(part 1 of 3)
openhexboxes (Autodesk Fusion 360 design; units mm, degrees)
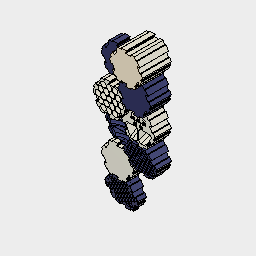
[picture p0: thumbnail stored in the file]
sketch "Skizze1"
  line L1 (20.2073, 35) -> (-20.2073, 35)
  line L2 (0, 0) -> (20.2073, 35)
  line L3 (-20.2073, 35) -> (0, 0)
  line L4 (0, 42) -> (0, 0)
  line L5 (-12.1732, 35) -> (-20.2073, 35)
  line L6 (-12.0866, 36.95) -> (-11.567, 36.05)
  line L7 (0.5196, 38) -> (-11.4804, 38)
  line L8 (-1.1258, 33.05) -> (1.1258, 36.95)
  line L9 (11.4804, 32) -> (-0.5196, 32)
  line L10 (11.567, 33.95) -> (12.0866, 33.05)
  line L11 (12.1732, 35) -> (20.2073, 35)
  line L12 (-20.2073, 35) -> (-40.4145, 0)
  line L13 (-29.1851, 15.55) -> (-31.4367, 19.45)
  line L14 (-24.2243, 28.0423) -> (-20.2073, 35)
  line L15 (-23.6181, 26.9923) -> (-22.5788, 26.9923)
  line L16 (-21.9726, 25.9423) -> (-27.9726, 15.55)
  line L17 (-32.6492, 19.45) -> (-38.6492, 9.0577)
  line L18 (-38.0429, 8.0077) -> (-37.0037, 8.0077)
  line L19 (-36.3975, 6.9577) -> (-40.4145, 0)
  line L20 (-40.4145, 0) -> (-20.2073, -35)
  line L21 (-28.0592, -17.5) -> (-32.5626, -17.5)
  line L22 (-36.3975, -6.9577) -> (-40.4145, 0)
  line L23 (-35.1851, -6.9577) -> (-34.6654, -6.0577)
  line L24 (-33.453, -6.0577) -> (-27.453, -16.45)
  line L25 (-33.1688, -18.55) -> (-27.1688, -28.9423)
  line L26 (-25.9563, -28.9423) -> (-25.4367, -28.0423)
  line L27 (-24.2243, -28.0423) -> (-20.2073, -35)
  line L28 (-20.2073, -35) -> (20.2073, -35)
  line L29 (1.1258, -33.05) -> (-1.1258, -36.95)
  line L30 (-12.1732, -35) -> (-20.2073, -35)
  line L31 (-11.567, -33.95) -> (-12.0866, -33.05)
  line L32 (-11.4804, -32) -> (0.5196, -32)
  line L33 (-0.5196, -38) -> (11.4804, -38)
  line L34 (12.0866, -36.95) -> (11.567, -36.05)
  line L35 (12.1732, -35) -> (20.2073, -35)
  line L36 (20.2073, -35) -> (40.4145, 0)
  line L37 (29.1851, -15.55) -> (31.4367, -19.45)
  line L38 (24.2243, -28.0423) -> (20.2073, -35)
  line L39 (23.6181, -26.9923) -> (22.5788, -26.9923)
  line L40 (21.9726, -25.9423) -> (27.9726, -15.55)
  line L41 (32.6492, -19.45) -> (38.6492, -9.0577)
  line L42 (38.0429, -8.0077) -> (37.0037, -8.0077)
  line L43 (36.3975, -6.9577) -> (40.4145, 0)
  line L44 (40.4145, 0) -> (20.2073, 35)
  line L45 (28.0592, 17.5) -> (32.5626, 17.5)
  line L46 (36.3975, 6.9577) -> (40.4145, 0)
  line L47 (35.1851, 6.9577) -> (34.6654, 6.0577)
  line L48 (33.453, 6.0577) -> (27.453, 16.45)
  line L49 (33.1688, 18.55) -> (27.1688, 28.9423)
  line L50 (25.9563, 28.9423) -> (25.4367, 28.0423)
  line L51 (24.2243, 28.0423) -> (20.2073, 35)
  arc A1 centre (-12.1732, 35.7) radius 0.7 clockwise from (-11.567, 36.05) to (-12.1732, 35)
  arc A2 centre (-11.4804, 37.3) radius 0.7 clockwise from (-12.0866, 36.95) to (-11.4804, 38)
  arc A3 centre (0.5196, 37.3) radius 0.7 clockwise from (0.5196, 38) to (1.1258, 36.95)
  arc A4 centre (-0.5196, 32.7) radius 0.7 clockwise from (-0.5196, 32) to (-1.1258, 33.05)
  arc A5 centre (11.4804, 32.7) radius 0.7 clockwise from (12.0866, 33.05) to (11.4804, 32)
  arc A6 centre (12.1732, 34.3) radius 0.7 clockwise from (11.567, 33.95) to (12.1732, 35)
  arc A7 centre (-22.5788, 26.2923) radius 0.7 clockwise from (-22.5788, 26.9923) to (-21.9726, 25.9423)
  arc A8 centre (-37.0037, 7.3077) radius 0.7 clockwise from (-37.0037, 8.0077) to (-36.3975, 6.9577)
  arc A9 centre (-38.0429, 8.7077) radius 0.7 clockwise from (-38.0429, 8.0077) to (-38.6492, 9.0577)
  arc A10 centre (-23.6181, 27.6923) radius 0.7 clockwise from (-23.6181, 26.9923) to (-24.2243, 28.0423)
  arc A11 centre (-32.0429, 19.1) radius 0.7 clockwise from (-32.6492, 19.45) to (-31.4367, 19.45)
  arc A12 centre (-28.5788, 15.9) radius 0.7 clockwise from (-27.9726, 15.55) to (-29.1851, 15.55)
  arc A13 centre (-34.0592, -6.4077) radius 0.7 clockwise from (-34.6654, -6.0577) to (-33.453, -6.0577)
  arc A14 centre (-24.8305, -28.3923) radius 0.7 clockwise from (-25.4367, -28.0423) to (-24.2243, -28.0423)
  arc A15 centre (-26.5626, -28.5923) radius 0.7 clockwise from (-25.9563, -28.9423) to (-27.1688, -28.9423)
  arc A16 centre (-35.7913, -6.6077) radius 0.7 clockwise from (-35.1851, -6.9577) to (-36.3975, -6.9577)
  arc A17 centre (-32.5626, -18.2) radius 0.7 clockwise from (-33.1688, -18.55) to (-32.5626, -17.5)
  arc A18 centre (-28.0592, -16.8) radius 0.7 clockwise from (-27.453, -16.45) to (-28.0592, -17.5)
  arc A19 centre (-11.4804, -32.7) radius 0.7 clockwise from (-12.0866, -33.05) to (-11.4804, -32)
  arc A20 centre (12.1732, -35.7) radius 0.7 clockwise from (11.567, -36.05) to (12.1732, -35)
  arc A21 centre (11.4804, -37.3) radius 0.7 clockwise from (12.0866, -36.95) to (11.4804, -38)
  arc A22 centre (-12.1732, -34.3) radius 0.7 clockwise from (-11.567, -33.95) to (-12.1732, -35)
  arc A23 centre (-0.5196, -37.3) radius 0.7 clockwise from (-0.5196, -38) to (-1.1258, -36.95)
  arc A24 centre (0.5196, -32.7) radius 0.7 clockwise from (0.5196, -32) to (1.1258, -33.05)
  arc A25 centre (22.5788, -26.2923) radius 0.7 clockwise from (22.5788, -26.9923) to (21.9726, -25.9423)
  arc A26 centre (37.0037, -7.3077) radius 0.7 clockwise from (37.0037, -8.0077) to (36.3975, -6.9577)
  arc A27 centre (38.0429, -8.7077) radius 0.7 clockwise from (38.0429, -8.0077) to (38.6492, -9.0577)
  arc A28 centre (23.6181, -27.6923) radius 0.7 clockwise from (23.6181, -26.9923) to (24.2243, -28.0423)
  arc A29 centre (32.0429, -19.1) radius 0.7 clockwise from (32.6492, -19.45) to (31.4367, -19.45)
  arc A30 centre (28.5788, -15.9) radius 0.7 clockwise from (27.9726, -15.55) to (29.1851, -15.55)
  arc A31 centre (34.0592, 6.4077) radius 0.7 clockwise from (34.6654, 6.0577) to (33.453, 6.0577)
  arc A32 centre (24.8305, 28.3923) radius 0.7 clockwise from (25.4367, 28.0423) to (24.2243, 28.0423)
  arc A33 centre (26.5626, 28.5923) radius 0.7 clockwise from (25.9563, 28.9423) to (27.1688, 28.9423)
  arc A34 centre (35.7913, 6.6077) radius 0.7 clockwise from (35.1851, 6.9577) to (36.3975, 6.9577)
  arc A35 centre (32.5626, 18.2) radius 0.7 clockwise from (33.1688, 18.55) to (32.5626, 17.5)
  arc A36 centre (28.0592, 16.8) radius 0.7 clockwise from (27.453, 16.45) to (28.0592, 17.5)
  point P1 (0, 0)
  point P11 (-11.4804, 38)
  point P13 (0.5196, 38)
  point P17 (-0.5196, 32)
  point P19 (11.4804, 32)
  dimension "d1" angle L2 L3 = 60
  dimension "d2" distance P1 L1 = 35
  dimension "d3" angle L3 L4 = 30
  dimension "d4" radius A1 = 0.7
  dimension "d5" distance L1 L7 = 3
  dimension "d6" distance L1 L9 = 3
  dimension "d7" angle L1 L8 = 60
  dimension "d8" angle L1 L10 = 60 (= "d7")
  dimension "d10" distance P11 P13 = 12
  dimension "d11" distance P17 P19 = 12 (= "d10")
  dimension "d13" C-Pattern1-Angle = 360
extrude "Extrusion1" sketch "Skizze1" profile of L5 L6 L7 L8 L9 L10 L11 A1 A2 A3 A4 A5 A6 A7 A8 A9 A10 L13 L14 L15 A11 A12 L16 L17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 blind 70 bodies "Basis"
sketch "Skizze2" plane through (0, 0, 70) normal (0, 0, 1) x axis (1, 0, 0)
  line L1 (12.0866, 33.05) -> (11.567, 33.95)
  line L2 (-0.5196, 32) -> (11.4804, 32)
  line L3 (1.1258, 36.95) -> (-1.1258, 33.05)
  line L4 (-11.4804, 38) -> (0.5196, 38)
  line L5 (-11.567, 36.05) -> (-12.0866, 36.95)
  line L6 (-20.2073, 35) -> (-12.1732, 35)
  line L7 (-24.2243, 28.0423) -> (-20.2073, 35)
  line L8 (-22.5788, 26.9923) -> (-23.6181, 26.9923)
  line L9 (-27.9726, 15.55) -> (-21.9726, 25.9423)
  line L10 (-31.4367, 19.45) -> (-29.1851, 15.55)
  line L11 (-38.6492, 9.0577) -> (-32.6492, 19.45)
  line L12 (-37.0037, 8.0077) -> (-38.0429, 8.0077)
  line L13 (-40.4145, 0) -> (-36.3975, 6.9577)
  line L14 (-36.3975, -6.9577) -> (-40.4145, 0)
  line L15 (-34.6654, -6.0577) -> (-35.1851, -6.9577)
  line L16 (-27.453, -16.45) -> (-33.453, -6.0577)
  line L17 (-32.5626, -17.5) -> (-28.0592, -17.5)
  line L18 (-27.1688, -28.9423) -> (-33.1688, -18.55)
  line L19 (-25.4367, -28.0423) -> (-25.9563, -28.9423)
  line L20 (-20.2073, -35) -> (-24.2243, -28.0423)
  line L21 (-12.1732, -35) -> (-20.2073, -35)
  line L22 (-12.0866, -33.05) -> (-11.567, -33.95)
  line L23 (0.5196, -32) -> (-11.4804, -32)
  line L24 (-1.1258, -36.95) -> (1.1258, -33.05)
  line L25 (11.4804, -38) -> (-0.5196, -38)
  line L26 (11.567, -36.05) -> (12.0866, -36.95)
  line L27 (20.2073, -35) -> (12.1732, -35)
  line L28 (24.2243, -28.0423) -> (20.2073, -35)
  line L29 (22.5788, -26.9923) -> (23.6181, -26.9923)
  line L30 (27.9726, -15.55) -> (21.9726, -25.9423)
  line L31 (31.4367, -19.45) -> (29.1851, -15.55)
  line L32 (38.6492, -9.0577) -> (32.6492, -19.45)
  line L33 (37.0037, -8.0077) -> (38.0429, -8.0077)
  line L34 (40.4145, 0) -> (36.3975, -6.9577)
  line L35 (36.3975, 6.9577) -> (40.4145, 0)
  line L36 (34.6654, 6.0577) -> (35.1851, 6.9577)
  line L37 (27.453, 16.45) -> (33.453, 6.0577)
  line L38 (32.5626, 17.5) -> (28.0592, 17.5)
  line L39 (27.1688, 28.9423) -> (33.1688, 18.55)
  line L40 (25.4367, 28.0423) -> (25.9563, 28.9423)
  line L41 (20.2073, 35) -> (24.2243, 28.0423)
  line L42 (12.1732, 35) -> (20.2073, 35)
  arc A1 centre (12.1732, 34.3) radius 0.7 clockwise from (11.567, 33.95) to (12.1732, 35)
  arc A2 centre (11.4804, 32.7) radius 0.7 clockwise from (12.0866, 33.05) to (11.4804, 32)
  arc A3 centre (-0.5196, 32.7) radius 0.7 clockwise from (-0.5196, 32) to (-1.1258, 33.05)
  arc A4 centre (0.5196, 37.3) radius 0.7 clockwise from (0.5196, 38) to (1.1258, 36.95)
  arc A5 centre (-11.4804, 37.3) radius 0.7 clockwise from (-12.0866, 36.95) to (-11.4804, 38)
  arc A6 centre (-12.1732, 35.7) radius 0.7 clockwise from (-11.567, 36.05) to (-12.1732, 35)
  arc A7 centre (-23.6181, 27.6923) radius 0.7 clockwise from (-23.6181, 26.9923) to (-24.2243, 28.0423)
  arc A8 centre (-22.5788, 26.2923) radius 0.7 clockwise from (-22.5788, 26.9923) to (-21.9726, 25.9423)
  arc A9 centre (-28.5788, 15.9) radius 0.7 clockwise from (-27.9726, 15.55) to (-29.1851, 15.55)
  arc A10 centre (-32.0429, 19.1) radius 0.7 clockwise from (-32.6492, 19.45) to (-31.4367, 19.45)
  arc A11 centre (-38.0429, 8.7077) radius 0.7 clockwise from (-38.0429, 8.0077) to (-38.6492, 9.0577)
  arc A12 centre (-37.0037, 7.3077) radius 0.7 clockwise from (-37.0037, 8.0077) to (-36.3975, 6.9577)
  arc A13 centre (-35.7913, -6.6077) radius 0.7 clockwise from (-35.1851, -6.9577) to (-36.3975, -6.9577)
  arc A14 centre (-34.0592, -6.4077) radius 0.7 clockwise from (-34.6654, -6.0577) to (-33.453, -6.0577)
  arc A15 centre (-28.0592, -16.8) radius 0.7 clockwise from (-27.453, -16.45) to (-28.0592, -17.5)
  arc A16 centre (-32.5626, -18.2) radius 0.7 clockwise from (-33.1688, -18.55) to (-32.5626, -17.5)
  arc A17 centre (-26.5626, -28.5923) radius 0.7 clockwise from (-25.9563, -28.9423) to (-27.1688, -28.9423)
  arc A18 centre (-24.8305, -28.3923) radius 0.7 clockwise from (-25.4367, -28.0423) to (-24.2243, -28.0423)
  arc A19 centre (-12.1732, -34.3) radius 0.7 clockwise from (-11.567, -33.95) to (-12.1732, -35)
  arc A20 centre (-11.4804, -32.7) radius 0.7 clockwise from (-12.0866, -33.05) to (-11.4804, -32)
  arc A21 centre (0.5196, -32.7) radius 0.7 clockwise from (0.5196, -32) to (1.1258, -33.05)
  arc A22 centre (-0.5196, -37.3) radius 0.7 clockwise from (-0.5196, -38) to (-1.1258, -36.95)
  arc A23 centre (11.4804, -37.3) radius 0.7 clockwise from (12.0866, -36.95) to (11.4804, -38)
  arc A24 centre (12.1732, -35.7) radius 0.7 clockwise from (11.567, -36.05) to (12.1732, -35)
  arc A25 centre (23.6181, -27.6923) radius 0.7 clockwise from (23.6181, -26.9923) to (24.2243, -28.0423)
  arc A26 centre (22.5788, -26.2923) radius 0.7 clockwise from (22.5788, -26.9923) to (21.9726, -25.9423)
  arc A27 centre (28.5788, -15.9) radius 0.7 clockwise from (27.9726, -15.55) to (29.1851, -15.55)
  arc A28 centre (32.0429, -19.1) radius 0.7 clockwise from (32.6492, -19.45) to (31.4367, -19.45)
  arc A29 centre (38.0429, -8.7077) radius 0.7 clockwise from (38.0429, -8.0077) to (38.6492, -9.0577)
  arc A30 centre (37.0037, -7.3077) radius 0.7 clockwise from (37.0037, -8.0077) to (36.3975, -6.9577)
  arc A31 centre (35.7913, 6.6077) radius 0.7 clockwise from (35.1851, 6.9577) to (36.3975, 6.9577)
  arc A32 centre (34.0592, 6.4077) radius 0.7 clockwise from (34.6654, 6.0577) to (33.453, 6.0577)
  arc A33 centre (28.0592, 16.8) radius 0.7 clockwise from (27.453, 16.45) to (28.0592, 17.5)
  arc A34 centre (32.5626, 18.2) radius 0.7 clockwise from (33.1688, 18.55) to (32.5626, 17.5)
  arc A35 centre (26.5626, 28.5923) radius 0.7 clockwise from (25.9563, 28.9423) to (27.1688, 28.9423)
  arc A36 centre (24.8305, 28.3923) radius 0.7 clockwise from (25.4367, 28.0423) to (24.2243, 28.0423)
sketch "Skizze3" plane through (0, 0, 0) normal (0, 0, -1) x axis (-1, 0, 0)
  line L1 (-20.2073, 35) -> (-12.1732, 35)
  line L2 (-24.2243, 28.0423) -> (-20.2073, 35)
  line L3 (-25.9563, 28.9423) -> (-25.4367, 28.0423)
  line L4 (-33.1688, 18.55) -> (-27.1688, 28.9423)
  line L5 (-28.0592, 17.5) -> (-32.5626, 17.5)
  line L6 (-33.453, 6.0577) -> (-27.453, 16.45)
  line L7 (-35.1851, 6.9577) -> (-34.6654, 6.0577)
  line L8 (-40.4145, 0) -> (-36.3975, 6.9577)
  line L9 (-36.3975, -6.9577) -> (-40.4145, 0)
  line L10 (-38.0429, -8.0077) -> (-37.0037, -8.0077)
  line L11 (-32.6492, -19.45) -> (-38.6492, -9.0577)
  line L12 (-29.1851, -15.55) -> (-31.4367, -19.45)
  line L13 (-21.9726, -25.9423) -> (-27.9726, -15.55)
  line L14 (-23.6181, -26.9923) -> (-22.5788, -26.9923)
  line L15 (-20.2073, -35) -> (-24.2243, -28.0423)
  line L16 (-12.1732, -35) -> (-20.2073, -35)
  line L17 (-12.0866, -36.95) -> (-11.567, -36.05)
  line L18 (0.5196, -38) -> (-11.4804, -38)
  line L19 (-1.1258, -33.05) -> (1.1258, -36.95)
  line L20 (11.4804, -32) -> (-0.5196, -32)
  line L21 (11.567, -33.95) -> (12.0866, -33.05)
  line L22 (20.2073, -35) -> (12.1732, -35)
  line L23 (24.2243, -28.0423) -> (20.2073, -35)
  line L24 (25.9563, -28.9423) -> (25.4367, -28.0423)
  line L25 (33.1688, -18.55) -> (27.1688, -28.9423)
  line L26 (28.0592, -17.5) -> (32.5626, -17.5)
  line L27 (33.453, -6.0577) -> (27.453, -16.45)
  line L28 (35.1851, -6.9577) -> (34.6654, -6.0577)
  line L29 (40.4145, 0) -> (36.3975, -6.9577)
  line L30 (36.3975, 6.9577) -> (40.4145, 0)
  line L31 (38.0429, 8.0077) -> (37.0037, 8.0077)
  line L32 (32.6492, 19.45) -> (38.6492, 9.0577)
  line L33 (29.1851, 15.55) -> (31.4367, 19.45)
  line L34 (21.9726, 25.9423) -> (27.9726, 15.55)
  line L35 (23.6181, 26.9923) -> (22.5788, 26.9923)
  line L36 (20.2073, 35) -> (24.2243, 28.0423)
  line L37 (12.1732, 35) -> (20.2073, 35)
  line L38 (12.0866, 36.95) -> (11.567, 36.05)
  line L39 (-0.5196, 38) -> (11.4804, 38)
  line L40 (1.1258, 33.05) -> (-1.1258, 36.95)
  line L41 (-11.4804, 32) -> (0.5196, 32)
  line L42 (-11.567, 33.95) -> (-12.0866, 33.05)
  line L43 (-28.0592, 17.7) -> (-32.5626, 17.7)
  line L44 (-33.2798, 5.9577) -> (-27.2798, 16.35)
  line L45 (-35.3583, 6.8577) -> (-34.8386, 5.9577)
  line L46 (-40.1836, 0) -> (-36.2243, 6.8577)
  line L47 (-36.2243, -6.8577) -> (-40.1836, 0)
  line L48 (-38.0429, -8.2077) -> (-37.0037, -8.2077)
  line L49 (-32.476, -19.35) -> (-38.476, -8.9577)
  line L50 (-29.3583, -15.45) -> (-31.6099, -19.35)
  line L51 (-21.7994, -25.8423) -> (-27.7994, -15.45)
  line L52 (-23.6181, -27.1923) -> (-22.5788, -27.1923)
  line L53 (-20.0918, -34.8) -> (-24.0511, -27.9423)
  line L54 (-12.1732, -34.8) -> (-20.0918, -34.8)
  line L55 (-11.9134, -37.05) -> (-11.3938, -36.15)
  line L56 (0.5196, -37.8) -> (-11.4804, -37.8)
  line L57 (-1.299, -33.15) -> (0.9526, -37.05)
  line L58 (11.4804, -31.8) -> (-0.5196, -31.8)
  line L59 (11.7402, -34.05) -> (12.2598, -33.15)
  line L60 (20.0918, -34.8) -> (12.1732, -34.8)
  line L61 (24.0511, -27.9423) -> (20.0918, -34.8)
  line L62 (26.1295, -28.8423) -> (25.6099, -27.9423)
  line L63 (32.9956, -18.45) -> (26.9956, -28.8423)
  line L64 (28.0592, -17.7) -> (32.5626, -17.7)
  line L65 (33.2798, -5.9577) -> (27.2798, -16.35)
  line L66 (35.3583, -6.8577) -> (34.8386, -5.9577)
  line L67 (40.1836, 0) -> (36.2243, -6.8577)
  line L68 (36.2243, 6.8577) -> (40.1836, 0)
  line L69 (38.0429, 8.2077) -> (37.0037, 8.2077)
  line L70 (32.476, 19.35) -> (38.476, 8.9577)
  line L71 (29.3583, 15.45) -> (31.6099, 19.35)
  line L72 (21.7994, 25.8423) -> (27.7994, 15.45)
  line L73 (23.6181, 27.1923) -> (22.5788, 27.1923)
  line L74 (20.0918, 34.8) -> (24.0511, 27.9423)
  line L75 (12.1732, 34.8) -> (20.0918, 34.8)
  line L76 (11.9134, 37.05) -> (11.3938, 36.15)
  line L77 (-0.5196, 37.8) -> (11.4804, 37.8)
  line L78 (1.299, 33.15) -> (-0.9526, 37.05)
  line L79 (-11.4804, 31.8) -> (0.5196, 31.8)
  line L80 (-11.7402, 34.05) -> (-12.2598, 33.15)
  line L81 (-20.0918, 34.8) -> (-12.1732, 34.8)
  line L82 (-24.0511, 27.9423) -> (-20.0918, 34.8)
  line L83 (-26.1295, 28.8423) -> (-25.6099, 27.9423)
  line L84 (-32.9956, 18.45) -> (-26.9956, 28.8423)
  arc A1 centre (-12.1732, 34.3) radius 0.7 clockwise from (-12.1732, 35) to (-11.567, 33.95)
  arc A2 centre (-24.8305, 28.3923) radius 0.7 clockwise from (-24.2243, 28.0423) to (-25.4367, 28.0423)
  arc A3 centre (-26.5626, 28.5923) radius 0.7 clockwise from (-27.1688, 28.9423) to (-25.9563, 28.9423)
  arc A4 centre (-32.5626, 18.2) radius 0.7 clockwise from (-32.5626, 17.5) to (-33.1688, 18.55)
  arc A5 centre (-28.0592, 16.8) radius 0.7 clockwise from (-28.0592, 17.5) to (-27.453, 16.45)
  arc A6 centre (-34.0592, 6.4077) radius 0.7 clockwise from (-33.453, 6.0577) to (-34.6654, 6.0577)
  arc A7 centre (-35.7913, 6.6077) radius 0.7 clockwise from (-36.3975, 6.9577) to (-35.1851, 6.9577)
  arc A8 centre (-37.0037, -7.3077) radius 0.7 clockwise from (-36.3975, -6.9577) to (-37.0037, -8.0077)
  arc A9 centre (-38.0429, -8.7077) radius 0.7 clockwise from (-38.6492, -9.0577) to (-38.0429, -8.0077)
  arc A10 centre (-32.0429, -19.1) radius 0.7 clockwise from (-31.4367, -19.45) to (-32.6492, -19.45)
  arc A11 centre (-28.5788, -15.9) radius 0.7 clockwise from (-29.1851, -15.55) to (-27.9726, -15.55)
  arc A12 centre (-22.5788, -26.2923) radius 0.7 clockwise from (-21.9726, -25.9423) to (-22.5788, -26.9923)
  arc A13 centre (-23.6181, -27.6923) radius 0.7 clockwise from (-24.2243, -28.0423) to (-23.6181, -26.9923)
  arc A14 centre (-12.1732, -35.7) radius 0.7 clockwise from (-12.1732, -35) to (-11.567, -36.05)
  arc A15 centre (-11.4804, -37.3) radius 0.7 clockwise from (-11.4804, -38) to (-12.0866, -36.95)
  arc A16 centre (0.5196, -37.3) radius 0.7 clockwise from (1.1258, -36.95) to (0.5196, -38)
  arc A17 centre (-0.5196, -32.7) radius 0.7 clockwise from (-1.1258, -33.05) to (-0.5196, -32)
  arc A18 centre (11.4804, -32.7) radius 0.7 clockwise from (11.4804, -32) to (12.0866, -33.05)
  arc A19 centre (12.1732, -34.3) radius 0.7 clockwise from (12.1732, -35) to (11.567, -33.95)
  arc A20 centre (24.8305, -28.3923) radius 0.7 clockwise from (24.2243, -28.0423) to (25.4367, -28.0423)
  arc A21 centre (26.5626, -28.5923) radius 0.7 clockwise from (27.1688, -28.9423) to (25.9563, -28.9423)
  arc A22 centre (32.5626, -18.2) radius 0.7 clockwise from (32.5626, -17.5) to (33.1688, -18.55)
  arc A23 centre (28.0592, -16.8) radius 0.7 clockwise from (28.0592, -17.5) to (27.453, -16.45)
  arc A24 centre (34.0592, -6.4077) radius 0.7 clockwise from (33.453, -6.0577) to (34.6654, -6.0577)
  arc A25 centre (35.7913, -6.6077) radius 0.7 clockwise from (36.3975, -6.9577) to (35.1851, -6.9577)
  arc A26 centre (37.0037, 7.3077) radius 0.7 clockwise from (36.3975, 6.9577) to (37.0037, 8.0077)
  arc A27 centre (38.0429, 8.7077) radius 0.7 clockwise from (38.6492, 9.0577) to (38.0429, 8.0077)
  arc A28 centre (32.0429, 19.1) radius 0.7 clockwise from (31.4367, 19.45) to (32.6492, 19.45)
  arc A29 centre (28.5788, 15.9) radius 0.7 clockwise from (29.1851, 15.55) to (27.9726, 15.55)
  arc A30 centre (22.5788, 26.2923) radius 0.7 clockwise from (21.9726, 25.9423) to (22.5788, 26.9923)
  arc A31 centre (23.6181, 27.6923) radius 0.7 clockwise from (24.2243, 28.0423) to (23.6181, 26.9923)
  arc A32 centre (12.1732, 35.7) radius 0.7 clockwise from (12.1732, 35) to (11.567, 36.05)
  arc A33 centre (11.4804, 37.3) radius 0.7 clockwise from (11.4804, 38) to (12.0866, 36.95)
  arc A34 centre (-0.5196, 37.3) radius 0.7 clockwise from (-1.1258, 36.95) to (-0.5196, 38)
  arc A35 centre (0.5196, 32.7) radius 0.7 clockwise from (1.1258, 33.05) to (0.5196, 32)
  arc A36 centre (-11.4804, 32.7) radius 0.7 clockwise from (-11.4804, 32) to (-12.0866, 33.05)
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  dimension "d16" = 0.2
extrude "Extrusion2" sketch "Skizze3" blind -70 bodies "vasemode_70"
copy_paste_bodies "Körper kopieren/einfügen1"
move "Verschieben1"
offset_faces "Flächen versetzen1" distance -20
copy_paste_bodies "Körper kopieren/einfügen2"
move "Verschieben2"
sketch "Skizze4" plane through (0, 0, 50) normal (0, 0, 1) x axis (1, 0, 0)
  line L1 (25.6099, -112.0577) -> (26.1295, -111.1577)
  line L2 (20.0918, -105.2) -> (24.0511, -112.0577)
  line L3 (12.1732, -105.2) -> (20.0918, -105.2)
  line L4 (12.2598, -106.85) -> (11.7402, -105.95)
  line L5 (-0.5196, -108.2) -> (11.4804, -108.2)
  line L6 (0.9526, -102.95) -> (-1.299, -106.85)
  line L7 (-11.4804, -102.2) -> (0.5196, -102.2)
  line L8 (-11.3938, -103.85) -> (-11.9134, -102.95)
  line L9 (-20.0918, -105.2) -> (-12.1732, -105.2)
  line L10 (-24.0511, -112.0577) -> (-20.0918, -105.2)
  line L11 (-22.5788, -112.8077) -> (-23.6181, -112.8077)
  line L12 (-27.7994, -124.55) -> (-21.7994, -114.1577)
  line L13 (-31.6099, -120.65) -> (-29.3583, -124.55)
  line L14 (-38.476, -131.0423) -> (-32.476, -120.65)
  line L15 (-37.0037, -131.7923) -> (-38.0429, -131.7923)
  line L16 (-40.1836, -140) -> (-36.2243, -133.1423)
  line L17 (-36.2243, -146.8577) -> (-40.1836, -140)
  line L18 (-34.8386, -145.9577) -> (-35.3583, -146.8577)
  line L19 (-27.2798, -156.35) -> (-33.2798, -145.9577)
  line L20 (-32.5626, -157.7) -> (-28.0592, -157.7)
  line L21 (-26.9956, -168.8423) -> (-32.9956, -158.45)
  line L22 (-25.6099, -167.9423) -> (-26.1295, -168.8423)
  line L23 (-20.0918, -174.8) -> (-24.0511, -167.9423)
  line L24 (-12.1732, -174.8) -> (-20.0918, -174.8)
  line L25 (-12.2598, -173.15) -> (-11.7402, -174.05)
  line L26 (0.5196, -171.8) -> (-11.4804, -171.8)
  line L27 (-0.9526, -177.05) -> (1.299, -173.15)
  line L28 (11.4804, -177.8) -> (-0.5196, -177.8)
  line L29 (11.3938, -176.15) -> (11.9134, -177.05)
  line L30 (20.0918, -174.8) -> (12.1732, -174.8)
  line L31 (24.0511, -167.9423) -> (20.0918, -174.8)
  line L32 (22.5788, -167.1923) -> (23.6181, -167.1923)
  line L33 (27.7994, -155.45) -> (21.7994, -165.8423)
  line L34 (31.6099, -159.35) -> (29.3583, -155.45)
  line L35 (38.476, -148.9577) -> (32.476, -159.35)
  line L36 (37.0037, -148.2077) -> (38.0429, -148.2077)
  line L37 (40.1836, -140) -> (36.2243, -146.8577)
  line L38 (36.2243, -133.1423) -> (40.1836, -140)
  line L39 (34.8386, -134.0423) -> (35.3583, -133.1423)
  line L40 (27.2798, -123.65) -> (33.2798, -134.0423)
  line L41 (32.5626, -122.3) -> (28.0592, -122.3)
  line L42 (26.9956, -111.1577) -> (32.9956, -121.55)
  line L43 (-13.6551, -118.2453) -> (13.6551, -118.2453)
  line L44 (-7.6189, -129.5701) -> (7.6189, -129.5701)
  line L45 (0, -250) -> (0, 0)
  arc A1 centre (24.8305, -111.6077) radius 0.9 clockwise from (25.6099, -112.0577) to (24.0511, -112.0577)
  arc A2 centre (12.1732, -105.7) radius 0.5 clockwise from (11.7402, -105.95) to (12.1732, -105.2)
  arc A3 centre (11.4804, -107.3) radius 0.9 clockwise from (12.2598, -106.85) to (11.4804, -108.2)
  arc A4 centre (-0.5196, -107.3) radius 0.9 clockwise from (-0.5196, -108.2) to (-1.299, -106.85)
  arc A5 centre (0.5196, -102.7) radius 0.5 clockwise from (0.5196, -102.2) to (0.9526, -102.95)
  arc A6 centre (-11.4804, -102.7) radius 0.5 clockwise from (-11.9134, -102.95) to (-11.4804, -102.2)
  arc A7 centre (-12.1732, -104.3) radius 0.9 clockwise from (-11.3938, -103.85) to (-12.1732, -105.2)
  arc A8 centre (-23.6181, -112.3077) radius 0.5 clockwise from (-23.6181, -112.8077) to (-24.0511, -112.0577)
  arc A9 centre (-22.5788, -113.7077) radius 0.9 clockwise from (-22.5788, -112.8077) to (-21.7994, -114.1577)
  arc A10 centre (-28.5788, -124.1) radius 0.9 clockwise from (-27.7994, -124.55) to (-29.3583, -124.55)
  arc A11 centre (-32.0429, -120.9) radius 0.5 clockwise from (-32.476, -120.65) to (-31.6099, -120.65)
  arc A12 centre (-38.0429, -131.2923) radius 0.5 clockwise from (-38.0429, -131.7923) to (-38.476, -131.0423)
  arc A13 centre (-37.0037, -132.6923) radius 0.9 clockwise from (-37.0037, -131.7923) to (-36.2243, -133.1423)
  arc A14 centre (-35.7913, -146.6077) radius 0.5 clockwise from (-35.3583, -146.8577) to (-36.2243, -146.8577)
  arc A15 centre (-34.0592, -146.4077) radius 0.9 clockwise from (-34.8386, -145.9577) to (-33.2798, -145.9577)
  arc A16 centre (-28.0592, -156.8) radius 0.9 clockwise from (-27.2798, -156.35) to (-28.0592, -157.7)
  arc A17 centre (-32.5626, -158.2) radius 0.5 clockwise from (-32.9956, -158.45) to (-32.5626, -157.7)
  arc A18 centre (-26.5626, -168.5923) radius 0.5 clockwise from (-26.1295, -168.8423) to (-26.9956, -168.8423)
  arc A19 centre (-24.8305, -168.3923) radius 0.9 clockwise from (-25.6099, -167.9423) to (-24.0511, -167.9423)
  arc A20 centre (-12.1732, -174.3) radius 0.5 clockwise from (-11.7402, -174.05) to (-12.1732, -174.8)
  arc A21 centre (-11.4804, -172.7) radius 0.9 clockwise from (-12.2598, -173.15) to (-11.4804, -171.8)
  arc A22 centre (0.5196, -172.7) radius 0.9 clockwise from (0.5196, -171.8) to (1.299, -173.15)
  arc A23 centre (-0.5196, -177.3) radius 0.5 clockwise from (-0.5196, -177.8) to (-0.9526, -177.05)
  arc A24 centre (11.4804, -177.3) radius 0.5 clockwise from (11.9134, -177.05) to (11.4804, -177.8)
  arc A25 centre (12.1732, -175.7) radius 0.9 clockwise from (11.3938, -176.15) to (12.1732, -174.8)
  arc A26 centre (23.6181, -167.6923) radius 0.5 clockwise from (23.6181, -167.1923) to (24.0511, -167.9423)
  arc A27 centre (22.5788, -166.2923) radius 0.9 clockwise from (22.5788, -167.1923) to (21.7994, -165.8423)
  arc A28 centre (28.5788, -155.9) radius 0.9 clockwise from (27.7994, -155.45) to (29.3583, -155.45)
  arc A29 centre (32.0429, -159.1) radius 0.5 clockwise from (32.476, -159.35) to (31.6099, -159.35)
  arc A30 centre (38.0429, -148.7077) radius 0.5 clockwise from (38.0429, -148.2077) to (38.476, -148.9577)
  arc A31 centre (37.0037, -147.3077) radius 0.9 clockwise from (37.0037, -148.2077) to (36.2243, -146.8577)
  arc A32 centre (35.7913, -133.3923) radius 0.5 clockwise from (35.3583, -133.1423) to (36.2243, -133.1423)
  arc A33 centre (34.0592, -133.5923) radius 0.9 clockwise from (34.8386, -134.0423) to (33.2798, -134.0423)
  arc A34 centre (28.0592, -123.2) radius 0.9 clockwise from (27.2798, -123.65) to (28.0592, -122.3)
  arc A35 centre (32.5626, -121.8) radius 0.5 clockwise from (32.9956, -121.55) to (32.5626, -122.3)
  arc A36 centre (26.5626, -111.4077) radius 0.5 clockwise from (26.1295, -111.1577) to (26.9956, -111.1577)
  circle C1 centre (-13.6551, -118.2453) radius 3.6
  circle C2 centre (0, -118.2453) radius 3.5
  circle C3 centre (13.6551, -118.2453) radius 3
  circle C4 centre (-7.6189, -129.5701) radius 2.5
  circle C5 centre (7.6189, -129.5701) radius 2.5
  dimension "d20" diameter C1 = 7.2
  dimension "d21" diameter C2 = 7
  dimension "d22" diameter C3 = 6
  dimension "d23" diameter C4 = 5
  dimension "d24" diameter C5 = 5
extrude "Extrusion3" sketch "Skizze4" profile of C1 C2 C3 C4 C5 blind -20
sketch "Skizze5" plane through (0, 0, 50) normal (0, 0, 1) x axis (1, 0, 0)
  line L1 (25.6099, -112.0577) -> (26.1295, -111.1577)
  line L2 (20.0918, -105.2) -> (24.0511, -112.0577)
  line L3 (12.1732, -105.2) -> (20.0918, -105.2)
  line L4 (12.2598, -106.85) -> (11.7402, -105.95)
  line L5 (-0.5196, -108.2) -> (11.4804, -108.2)
  line L6 (0.9526, -102.95) -> (-1.299, -106.85)
  line L7 (-11.4804, -102.2) -> (0.5196, -102.2)
  line L8 (-11.3938, -103.85) -> (-11.9134, -102.95)
  line L9 (-20.0918, -105.2) -> (-12.1732, -105.2)
  line L10 (-24.0511, -112.0577) -> (-20.0918, -105.2)
  line L11 (-22.5788, -112.8077) -> (-23.6181, -112.8077)
  line L12 (-27.7994, -124.55) -> (-21.7994, -114.1577)
  line L13 (-31.6099, -120.65) -> (-29.3583, -124.55)
  line L14 (-38.476, -131.0423) -> (-32.476, -120.65)
  line L15 (-37.0037, -131.7923) -> (-38.0429, -131.7923)
  line L16 (-40.1836, -140) -> (-36.2243, -133.1423)
  line L17 (-36.2243, -146.8577) -> (-40.1836, -140)
  line L18 (-34.8386, -145.9577) -> (-35.3583, -146.8577)
  line L19 (-27.2798, -156.35) -> (-33.2798, -145.9577)
  line L20 (-32.5626, -157.7) -> (-28.0592, -157.7)
  line L21 (-26.9956, -168.8423) -> (-32.9956, -158.45)
  line L22 (-25.6099, -167.9423) -> (-26.1295, -168.8423)
  line L23 (-20.0918, -174.8) -> (-24.0511, -167.9423)
  line L24 (-12.1732, -174.8) -> (-20.0918, -174.8)
  line L25 (-12.2598, -173.15) -> (-11.7402, -174.05)
  line L26 (0.5196, -171.8) -> (-11.4804, -171.8)
  line L27 (-0.9526, -177.05) -> (1.299, -173.15)
  line L28 (11.4804, -177.8) -> (-0.5196, -177.8)
  line L29 (11.3938, -176.15) -> (11.9134, -177.05)
  line L30 (20.0918, -174.8) -> (12.1732, -174.8)
  line L31 (24.0511, -167.9423) -> (20.0918, -174.8)
  line L32 (22.5788, -167.1923) -> (23.6181, -167.1923)
  line L33 (27.7994, -155.45) -> (21.7994, -165.8423)
  line L34 (31.6099, -159.35) -> (29.3583, -155.45)
  line L35 (38.476, -148.9577) -> (32.476, -159.35)
  line L36 (37.0037, -148.2077) -> (38.0429, -148.2077)
  line L37 (40.1836, -140) -> (36.2243, -146.8577)
  line L38 (36.2243, -133.1423) -> (40.1836, -140)
  line L39 (34.8386, -134.0423) -> (35.3583, -133.1423)
  line L40 (27.2798, -123.65) -> (33.2798, -134.0423)
  line L41 (32.5626, -122.3) -> (28.0592, -122.3)
  line L42 (26.9956, -111.1577) -> (32.9956, -121.55)
  curve K1 (-9.7239, -127.0197) -> (-17.4202, -127.0197)
  curve K2 (-9.7239, -121.0197) -> (-9.7239, -127.0197)
  curve K3 (-17.4202, -121.0197) -> (-9.7239, -121.0197)
  curve K4 (-17.4202, -127.0197) -> (-17.4202, -121.0197)
  curve K5 (11.5003, -137.3718) -> (3.8128, -137.3718)
  curve K6 (11.5003, -131.3718) -> (11.5003, -137.3718)
  curve K7 (3.8128, -131.3718) -> (11.5003, -131.3718)
  curve K8 (3.8128, -137.3718) -> (3.8128, -131.3718)
  curve K9 (-3.5173, -137.3718) -> (-11.1872, -137.3718)
  curve K10 (-3.5173, -131.3718) -> (-3.5173, -137.3718)
  curve K11 (-11.1872, -131.3718) -> (-3.5173, -131.3718)
  curve K12 (-11.1872, -137.3718) -> (-11.1872, -131.3718)
  curve K13 (18.2995, -127.0197) -> (10.5798, -127.0197)
  curve K14 (18.2995, -121.0197) -> (18.2995, -127.0197)
  curve K15 (10.5798, -121.0197) -> (18.2995, -121.0197)
  curve K16 (10.5798, -127.0197) -> (10.5798, -121.0197)
  curve K17 (4.2673, -127.0197) -> (-3.4202, -127.0197)
  curve K18 (4.2673, -121.0197) -> (4.2673, -127.0197)
  curve K19 (-3.4202, -121.0197) -> (4.2673, -121.0197)
  curve K20 (-3.4202, -127.0197) -> (-3.4202, -121.0197)
  circle C1 centre (7.6189, -129.5701) radius 2.5
  circle C2 centre (-7.6189, -129.5701) radius 2.5
  circle C3 centre (0, -118.2453) radius 3.5
  circle C4 centre (-13.6551, -118.2453) radius 3.6
  circle C5 centre (13.6551, -118.2453) radius 3
  arc A1 centre (24.8305, -111.6077) radius 0.9 clockwise from (25.6099, -112.0577) to (24.0511, -112.0577)
  arc A2 centre (12.1732, -105.7) radius 0.5 clockwise from (11.7402, -105.95) to (12.1732, -105.2)
  arc A3 centre (11.4804, -107.3) radius 0.9 clockwise from (12.2598, -106.85) to (11.4804, -108.2)
  arc A4 centre (-0.5196, -107.3) radius 0.9 clockwise from (-0.5196, -108.2) to (-1.299, -106.85)
  arc A5 centre (0.5196, -102.7) radius 0.5 clockwise from (0.5196, -102.2) to (0.9526, -102.95)
  arc A6 centre (-11.4804, -102.7) radius 0.5 clockwise from (-11.9134, -102.95) to (-11.4804, -102.2)
  arc A7 centre (-12.1732, -104.3) radius 0.9 clockwise from (-11.3938, -103.85) to (-12.1732, -105.2)
  arc A8 centre (-23.6181, -112.3077) radius 0.5 clockwise from (-23.6181, -112.8077) to (-24.0511, -112.0577)
  arc A9 centre (-22.5788, -113.7077) radius 0.9 clockwise from (-22.5788, -112.8077) to (-21.7994, -114.1577)
  arc A10 centre (-28.5788, -124.1) radius 0.9 clockwise from (-27.7994, -124.55) to (-29.3583, -124.55)
  arc A11 centre (-32.0429, -120.9) radius 0.5 clockwise from (-32.476, -120.65) to (-31.6099, -120.65)
  arc A12 centre (-38.0429, -131.2923) radius 0.5 clockwise from (-38.0429, -131.7923) to (-38.476, -131.0423)
  arc A13 centre (-37.0037, -132.6923) radius 0.9 clockwise from (-37.0037, -131.7923) to (-36.2243, -133.1423)
  arc A14 centre (-35.7913, -146.6077) radius 0.5 clockwise from (-35.3583, -146.8577) to (-36.2243, -146.8577)
  arc A15 centre (-34.0592, -146.4077) radius 0.9 clockwise from (-34.8386, -145.9577) to (-33.2798, -145.9577)
  arc A16 centre (-28.0592, -156.8) radius 0.9 clockwise from (-27.2798, -156.35) to (-28.0592, -157.7)
  arc A17 centre (-32.5626, -158.2) radius 0.5 clockwise from (-32.9956, -158.45) to (-32.5626, -157.7)
  arc A18 centre (-26.5626, -168.5923) radius 0.5 clockwise from (-26.1295, -168.8423) to (-26.9956, -168.8423)
  arc A19 centre (-24.8305, -168.3923) radius 0.9 clockwise from (-25.6099, -167.9423) to (-24.0511, -167.9423)
  arc A20 centre (-12.1732, -174.3) radius 0.5 clockwise from (-11.7402, -174.05) to (-12.1732, -174.8)
  arc A21 centre (-11.4804, -172.7) radius 0.9 clockwise from (-12.2598, -173.15) to (-11.4804, -171.8)
  arc A22 centre (0.5196, -172.7) radius 0.9 clockwise from (0.5196, -171.8) to (1.299, -173.15)
  arc A23 centre (-0.5196, -177.3) radius 0.5 clockwise from (-0.5196, -177.8) to (-0.9526, -177.05)
  arc A24 centre (11.4804, -177.3) radius 0.5 clockwise from (11.9134, -177.05) to (11.4804, -177.8)
  arc A25 centre (12.1732, -175.7) radius 0.9 clockwise from (11.3938, -176.15) to (12.1732, -174.8)
  arc A26 centre (23.6181, -167.6923) radius 0.5 clockwise from (23.6181, -167.1923) to (24.0511, -167.9423)
  arc A27 centre (22.5788, -166.2923) radius 0.9 clockwise from (22.5788, -167.1923) to (21.7994, -165.8423)
  arc A28 centre (28.5788, -155.9) radius 0.9 clockwise from (27.7994, -155.45) to (29.3583, -155.45)
  arc A29 centre (32.0429, -159.1) radius 0.5 clockwise from (32.476, -159.35) to (31.6099, -159.35)
  arc A30 centre (38.0429, -148.7077) radius 0.5 clockwise from (38.0429, -148.2077) to (38.476, -148.9577)
  arc A31 centre (37.0037, -147.3077) radius 0.9 clockwise from (37.0037, -148.2077) to (36.2243, -146.8577)
  arc A32 centre (35.7913, -133.3923) radius 0.5 clockwise from (35.3583, -133.1423) to (36.2243, -133.1423)
  arc A33 centre (34.0592, -133.5923) radius 0.9 clockwise from (34.8386, -134.0423) to (33.2798, -134.0423)
  arc A34 centre (28.0592, -123.2) radius 0.9 clockwise from (27.2798, -123.65) to (28.0592, -122.3)
  arc A35 centre (32.5626, -121.8) radius 0.5 clockwise from (32.9956, -121.55) to (32.5626, -122.3)
  arc A36 centre (26.5626, -111.4077) radius 0.5 clockwise from (26.1295, -111.1577) to (26.9956, -111.1577)
sketch "Skizze6" plane through (0, 0, 50) normal (0, 0, 1) x axis (1, 0, 0)
  line L1 (17.436, -170.2) -> (34.7565, -140.2)
  line L2 (-34.7565, -140.2) -> (-17.436, -170.2)
  line L3 (27.7994, -155.45) -> (21.7994, -165.8423)
  line L4 (-27.2798, -156.35) -> (-33.2798, -145.9577)
  line L5 (0.5196, -171.8) -> (-11.4804, -171.8)
  line L6 (-1, -170.2) -> (-1, -140.2)
  line L7 (1, -170.2) -> (1, -140.2)
  line L8 (1, -170.2) -> (17.436, -170.2)
  line L9 (-17.436, -170.2) -> (-1, -170.2)
  line L10 (-1, -140.2) -> (-34.7565, -140.2)
  line L11 (34.7565, -140.2) -> (1, -140.2)
  dimension "d27" distance L1 L3 = 1.6
  dimension "d28" distance L5 L8 = 1.6
  dimension "d29" distance L2 L4 = 1.6
  dimension "d30" distance L8 L10 = 30
  dimension "d31" distance L6 L7 = 2
extrude "Extrusion4" sketch "Skizze6" profile of L11 L1 L9 L2 L6 L7 blind -35
move_face "Fläche verschieben1"
fillet "Abrundung1" radius 5
extrude "Extrusion5" add sketch "Skizze5" along normal blind 1
offset_faces "Flächen versetzen2" distance -10
copy_paste_bodies "Körper kopieren/einfügen3"
move "Verschieben3"
move "Verschieben4"
offset_faces "Flächen versetzen3" distance -20
sketch "Skizze7" plane through (0, 0, 30) normal (0, 0, 1) x axis (1, 0, 0)
  line L1 (25.6099, -182.0577) -> (26.1295, -181.1577)
  line L2 (20.0918, -175.2) -> (24.0511, -182.0577)
  line L3 (12.1732, -175.2) -> (20.0918, -175.2)
  line L4 (12.2598, -176.85) -> (11.7402, -175.95)
  line L5 (-0.5196, -178.2) -> (11.4804, -178.2)
  line L6 (0.9526, -172.95) -> (-1.299, -176.85)
  line L7 (-11.4804, -172.2) -> (0.5196, -172.2)
  line L8 (-11.3938, -173.85) -> (-11.9134, -172.95)
  line L9 (-20.0918, -175.2) -> (-12.1732, -175.2)
  line L10 (-24.0511, -182.0577) -> (-20.0918, -175.2)
  line L11 (-22.5788, -182.8077) -> (-23.6181, -182.8077)
  line L12 (-27.7994, -194.55) -> (-21.7994, -184.1577)
  line L13 (-31.6099, -190.65) -> (-29.3583, -194.55)
  line L14 (-38.476, -201.0423) -> (-32.476, -190.65)
  line L15 (-37.0037, -201.7923) -> (-38.0429, -201.7923)
  line L16 (-40.1836, -210) -> (-36.2243, -203.1423)
  line L17 (-36.2243, -216.8577) -> (-40.1836, -210)
  line L18 (-34.8386, -215.9577) -> (-35.3583, -216.8577)
  line L19 (-27.2798, -226.35) -> (-33.2798, -215.9577)
  line L20 (-32.5626, -227.7) -> (-28.0592, -227.7)
  line L21 (-26.9956, -238.8423) -> (-32.9956, -228.45)
  line L22 (-25.6099, -237.9423) -> (-26.1295, -238.8423)
  line L23 (-20.0918, -244.8) -> (-24.0511, -237.9423)
  line L24 (-12.1732, -244.8) -> (-20.0918, -244.8)
  line L25 (-12.2598, -243.15) -> (-11.7402, -244.05)
  line L26 (0.5196, -241.8) -> (-11.4804, -241.8)
  line L27 (-0.9526, -247.05) -> (1.299, -243.15)
  line L28 (11.4804, -247.8) -> (-0.5196, -247.8)
  line L29 (11.3938, -246.15) -> (11.9134, -247.05)
  line L30 (20.0918, -244.8) -> (12.1732, -244.8)
  line L31 (24.0511, -237.9423) -> (20.0918, -244.8)
  line L32 (22.5788, -237.1923) -> (23.6181, -237.1923)
  line L33 (27.7994, -225.45) -> (21.7994, -235.8423)
  line L34 (31.6099, -229.35) -> (29.3583, -225.45)
  line L35 (38.476, -218.9577) -> (32.476, -229.35)
  line L36 (37.0037, -218.2077) -> (38.0429, -218.2077)
  line L37 (40.1836, -210) -> (36.2243, -216.8577)
  line L38 (36.2243, -203.1423) -> (40.1836, -210)
  line L39 (34.8386, -204.0423) -> (35.3583, -203.1423)
  line L40 (27.2798, -193.65) -> (33.2798, -204.0423)
  line L41 (32.5626, -192.3) -> (28.0592, -192.3)
  line L42 (26.9956, -181.1577) -> (32.9956, -191.55)
  line L43 (0.5196, -32) -> (-11.4804, -32)
  line L44 (0, -400) -> (0, 0)
  line L45 (40.1836, -210) -> (-40.1836, -210)
  arc A1 centre (24.8305, -181.6077) radius 0.9 clockwise from (25.6099, -182.0577) to (24.0511, -182.0577)
  arc A2 centre (12.1732, -175.7) radius 0.5 clockwise from (11.7402, -175.95) to (12.1732, -175.2)
  arc A3 centre (11.4804, -177.3) radius 0.9 clockwise from (12.2598, -176.85) to (11.4804, -178.2)
  arc A4 centre (-0.5196, -177.3) radius 0.9 clockwise from (-0.5196, -178.2) to (-1.299, -176.85)
  arc A5 centre (0.5196, -172.7) radius 0.5 clockwise from (0.5196, -172.2) to (0.9526, -172.95)
  arc A6 centre (-11.4804, -172.7) radius 0.5 clockwise from (-11.9134, -172.95) to (-11.4804, -172.2)
  arc A7 centre (-12.1732, -174.3) radius 0.9 clockwise from (-11.3938, -173.85) to (-12.1732, -175.2)
  arc A8 centre (-23.6181, -182.3077) radius 0.5 clockwise from (-23.6181, -182.8077) to (-24.0511, -182.0577)
  arc A9 centre (-22.5788, -183.7077) radius 0.9 clockwise from (-22.5788, -182.8077) to (-21.7994, -184.1577)
  arc A10 centre (-28.5788, -194.1) radius 0.9 clockwise from (-27.7994, -194.55) to (-29.3583, -194.55)
  arc A11 centre (-32.0429, -190.9) radius 0.5 clockwise from (-32.476, -190.65) to (-31.6099, -190.65)
  arc A12 centre (-38.0429, -201.2923) radius 0.5 clockwise from (-38.0429, -201.7923) to (-38.476, -201.0423)
  arc A13 centre (-37.0037, -202.6923) radius 0.9 clockwise from (-37.0037, -201.7923) to (-36.2243, -203.1423)
  arc A14 centre (-35.7913, -216.6077) radius 0.5 clockwise from (-35.3583, -216.8577) to (-36.2243, -216.8577)
  arc A15 centre (-34.0592, -216.4077) radius 0.9 clockwise from (-34.8386, -215.9577) to (-33.2798, -215.9577)
  arc A16 centre (-28.0592, -226.8) radius 0.9 clockwise from (-27.2798, -226.35) to (-28.0592, -227.7)
  arc A17 centre (-32.5626, -228.2) radius 0.5 clockwise from (-32.9956, -228.45) to (-32.5626, -227.7)
  arc A18 centre (-26.5626, -238.5923) radius 0.5 clockwise from (-26.1295, -238.8423) to (-26.9956, -238.8423)
  arc A19 centre (-24.8305, -238.3923) radius 0.9 clockwise from (-25.6099, -237.9423) to (-24.0511, -237.9423)
  arc A20 centre (-12.1732, -244.3) radius 0.5 clockwise from (-11.7402, -244.05) to (-12.1732, -244.8)
  arc A21 centre (-11.4804, -242.7) radius 0.9 clockwise from (-12.2598, -243.15) to (-11.4804, -241.8)
  arc A22 centre (0.5196, -242.7) radius 0.9 clockwise from (0.5196, -241.8) to (1.299, -243.15)
  arc A23 centre (-0.5196, -247.3) radius 0.5 clockwise from (-0.5196, -247.8) to (-0.9526, -247.05)
  arc A24 centre (11.4804, -247.3) radius 0.5 clockwise from (11.9134, -247.05) to (11.4804, -247.8)
  arc A25 centre (12.1732, -245.7) radius 0.9 clockwise from (11.3938, -246.15) to (12.1732, -244.8)
  arc A26 centre (23.6181, -237.6923) radius 0.5 clockwise from (23.6181, -237.1923) to (24.0511, -237.9423)
  arc A27 centre (22.5788, -236.2923) radius 0.9 clockwise from (22.5788, -237.1923) to (21.7994, -235.8423)
  arc A28 centre (28.5788, -225.9) radius 0.9 clockwise from (27.7994, -225.45) to (29.3583, -225.45)
  arc A29 centre (32.0429, -229.1) radius 0.5 clockwise from (32.476, -229.35) to (31.6099, -229.35)
  arc A30 centre (38.0429, -218.7077) radius 0.5 clockwise from (38.0429, -218.2077) to (38.476, -218.9577)
  arc A31 centre (37.0037, -217.3077) radius 0.9 clockwise from (37.0037, -218.2077) to (36.2243, -216.8577)
  arc A32 centre (35.7913, -203.3923) radius 0.5 clockwise from (35.3583, -203.1423) to (36.2243, -203.1423)
  arc A33 centre (34.0592, -203.5923) radius 0.9 clockwise from (34.8386, -204.0423) to (33.2798, -204.0423)
  arc A34 centre (28.0592, -193.2) radius 0.9 clockwise from (27.2798, -193.65) to (28.0592, -192.3)
  arc A35 centre (32.5626, -191.8) radius 0.5 clockwise from (32.9956, -191.55) to (32.5626, -192.3)
  arc A36 centre (26.5626, -181.4077) radius 0.5 clockwise from (26.1295, -181.1577) to (26.9956, -181.1577)
  circle C1 centre (0, -210) radius 3.5
  circle C2 centre (16, -182.2872) radius 3.5
  circle C3 centre (20, -189.2154) radius 3.5
  circle C4 centre (24, -196.1436) radius 3.5
  circle C5 centre (28, -203.0718) radius 3.5
  circle C6 centre (32, -210) radius 3.5
  circle C7 centre (8, -182.2872) radius 3.5
  circle C8 centre (12, -189.2154) radius 3.5
  circle C9 centre (16, -196.1436) radius 3.5
  circle C10 centre (20, -203.0718) radius 3.5
  circle C11 centre (24, -210) radius 3.5
  circle C12 centre (28, -216.9282) radius 3.5
  circle C13 centre (0, -182.2872) radius 3.5
  circle C14 centre (4, -189.2154) radius 3.5
  circle C15 centre (8, -196.1436) radius 3.5
  circle C16 centre (12, -203.0718) radius 3.5
  circle C17 centre (16, -210) radius 3.5
  circle C18 centre (20, -216.9282) radius 3.5
  circle C19 centre (24, -223.8564) radius 3.5
  circle C20 centre (-8, -182.2872) radius 3.5
  circle C21 centre (-4, -189.2154) radius 3.5
  circle C22 centre (0, -196.1436) radius 3.5
  circle C23 centre (4, -203.0718) radius 3.5
  circle C24 centre (8, -210) radius 3.5
  circle C25 centre (12, -216.9282) radius 3.5
  circle C26 centre (16, -223.8564) radius 3.5
  circle C27 centre (20, -230.7846) radius 3.5
  circle C28 centre (-16, -182.2872) radius 3.5
  circle C29 centre (-12, -189.2154) radius 3.5
  circle C30 centre (-8, -196.1436) radius 3.5
  circle C31 centre (-4, -203.0718) radius 3.5
  circle C32 centre (4, -216.9282) radius 3.5
  circle C33 centre (8, -223.8564) radius 3.5
  circle C34 centre (12, -230.7846) radius 3.5
  circle C35 centre (16, -237.7128) radius 3.5
  circle C36 centre (-20, -189.2154) radius 3.5
  circle C37 centre (-16, -196.1436) radius 3.5
  circle C38 centre (-12, -203.0718) radius 3.5
  circle C39 centre (-8, -210) radius 3.5
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  dimension "d39" diameter C1 = 7
  dimension "d45" R-Pattern1-uDistance = 8
  dimension "d46" R-Pattern1-vDistance = 8
extrude "Extrusion6" sketch "Skizze7" blind -29
move_face "Fläche verschieben2"
copy_paste_bodies "Körper kopieren/einfügen4"
move "Verschieben5"
copy_paste_bodies "Körper kopieren/einfügen5"
move "Verschieben6"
